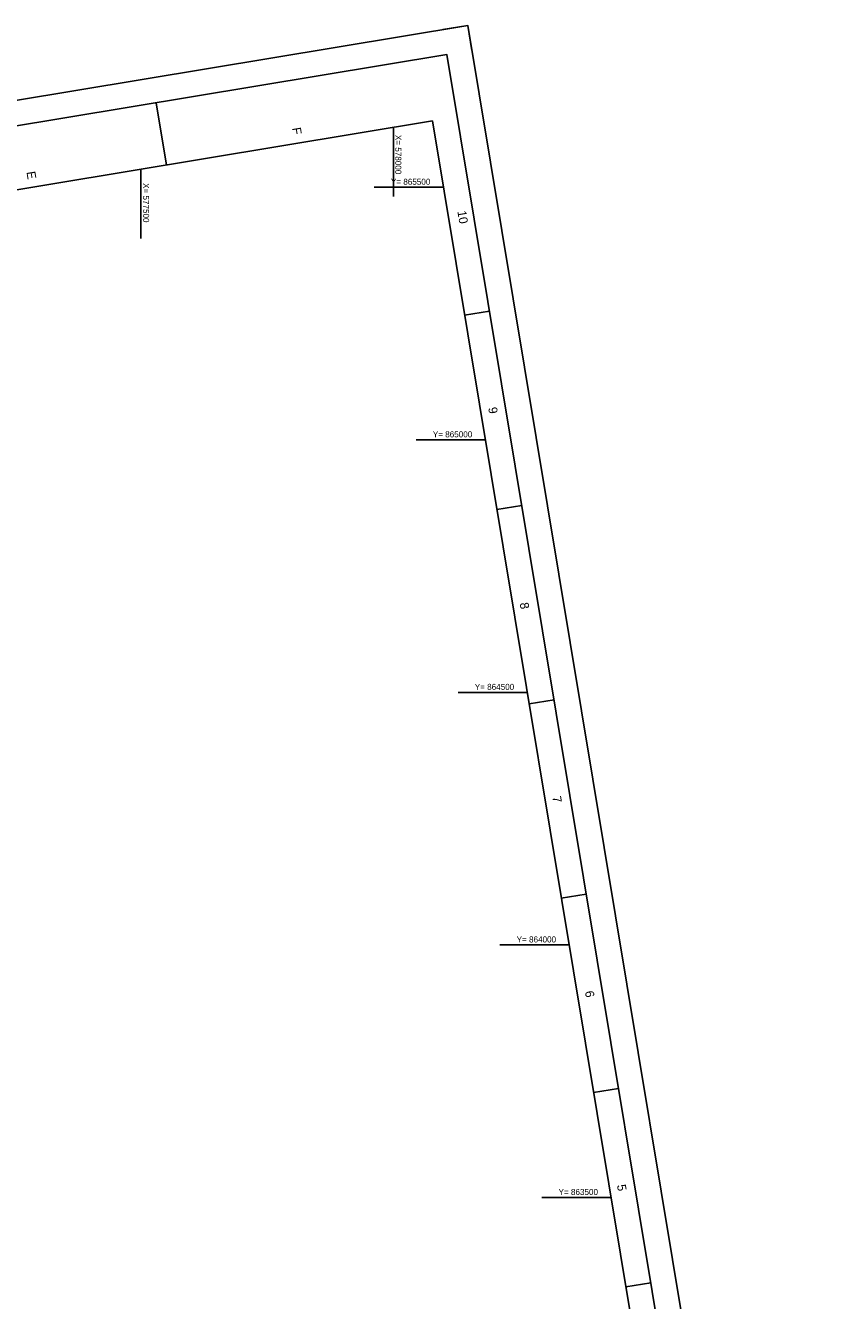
# Model space of a CAD drawing. Extents: x 574793 to 578867, y 860923 to 865820.
# Drawn here: x 577272 to 578867, y 863296 to 865820 of the extents above; entities that cross this region are included whole.
import ezdxf

# ---------------------------------------------------------------- set-up
doc = ezdxf.new("R2010")
doc.units = 0
for name, color, linetype in [('G-ANNO-NPLT', 7, 'Continuous'), ('G-ANNO-TTLB', 7, 'Continuous'), ('V-TOPO-COOR-STAT', 7, 'Continuous')]:
    doc.layers.add(name, color=color, linetype=linetype)

msp = doc.modelspace()

# ---------------------------------------------------------------- linework, layer by layer
at = {"layer": 'G-ANNO-NPLT'}
msp.add_lwpolyline([(578147.3, 865820.4), (578867.1, 861479.7), (575512.9, 860923.5), (574793.1, 865264.2)], close=True, dxfattribs=at)
msp.add_lwpolyline([(578097.9, 865812.2), (578147.3, 865820.4), (578155.4, 865771.1)], dxfattribs=at)
at = {"layer": 'G-ANNO-TTLB'}
for p, q in [((577530.5, 865667.4), (577550.9, 865544.1)), ((578190.4, 865254.8), (578141, 865246.6)), ((578254.2, 864870.1), (578204.8, 864861.9)), ((578254.2, 864870.1), (578204.8, 864861.9)), ((578318, 864485.3), (578268.6, 864477.1)), ((578381.8, 864100.6), (578332.4, 864092.4)), ((578445.6, 863715.8), (578396.2, 863707.7)), ((578509.4, 863331.1), (578460, 863322.9))]:
    msp.add_line(p, q, dxfattribs=at)
for points in [[(574850.6, 865223), (575554, 860981), (578809.6, 861520.8), (578106.1, 865762.9)], [(578752.1, 861562), (578077.2, 865631.4), (574920.4, 865107.9), (575595.2, 861038.5)]]:
    msp.add_lwpolyline(points, close=True, dxfattribs=at)
at = {"layer": 'V-TOPO-COOR-STAT'}
for p, q in [((578000, 865481.7), (578000, 865618.6)), ((577500, 865398.8), (577500, 865535.7)), ((577962.2, 865500), (578099, 865500)), ((578045.1, 865000), (578181.9, 865000)), ((578128, 864500), (578264.9, 864500)), ((578210.9, 864000), (578347.8, 864000)), ((578293.8, 863500), (578430.7, 863500))]:
    msp.add_line(p, q, dxfattribs=at)

# ---------------------------------------------------------------- texts
at = {"layer": 'G-ANNO-TTLB'}
for s, p in [('F', (577799.4, 865617.2)), ('E', (577273.9, 865530.2)), ('10', (578126.6, 865452.5)), ('9', (578187.6, 865063.4)), ('8', (578250, 864676.7)), ('7', (578314.3, 864293.3)), ('6', (578379, 863907.8)), ('5', (578442.5, 863524.5))]:
    msp.add_text(s, height=17.5, rotation=279.4155, dxfattribs=at).set_placement(p)
at = {"layer": 'V-TOPO-COOR-STAT'}
for s, p in [('X= 578000', (578003.8, 865603.8)), ('X= 577500', (577504.7, 865508.4))]:
    msp.add_text(s, height=12, rotation=270, dxfattribs=at).set_placement(p)
for s, p in [('Y= 865500', (577995.2, 865505)), ('Y= 865000', (578078.1, 865005)), ('Y= 864500', (578161.1, 864505)), ('Y= 864000', (578244, 864005)), ('Y= 863500', (578326.9, 863505))]:
    msp.add_text(s, height=12, dxfattribs=at).set_placement(p)

doc.saveas('drawing.dxf')
